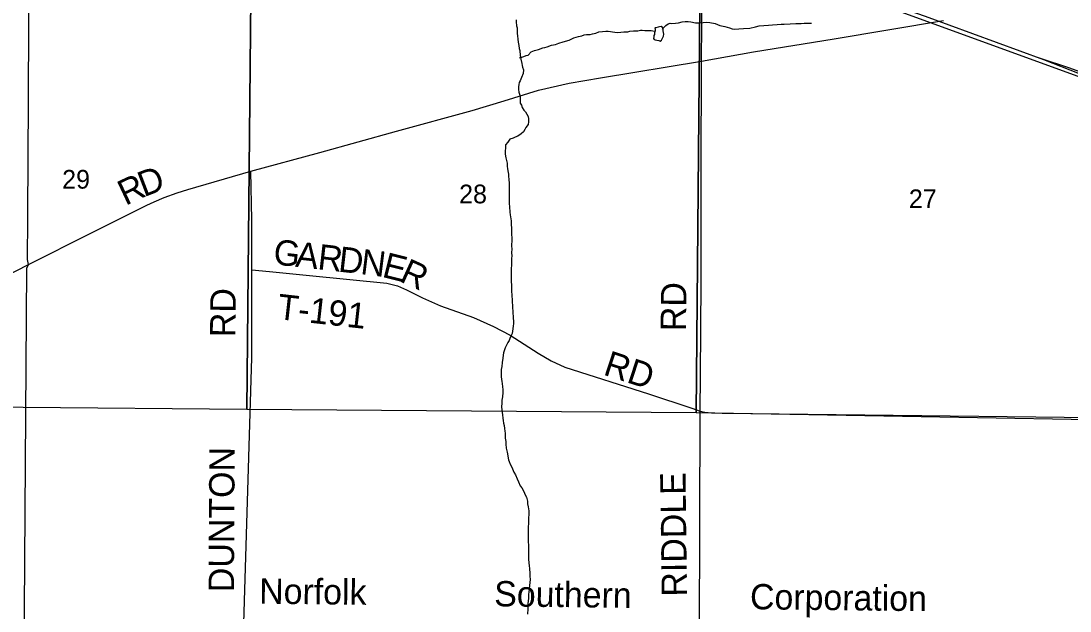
# Model space of a CAD drawing. Extents: x 0 to 34, y 0 to 22.
# Drawn here: x 4.651 to 6.998, y 14.74 to 16.061 of the extents above; entities that cross this region are included whole.
import ezdxf

# ---------------------------------------------------------------- set-up
doc = ezdxf.new("R2010")
doc.units = 0
for name, color, linetype in [('GM_X_County_Road', 7, 'Continuous'), ('GM_X_County_Road_Text', 7, 'Continuous'), ('GM_X_Minor_Lake', 7, 'Continuous'), ('GM_X_Minor_River', 7, 'Continuous'), ('GM_X_Rail_Line', 7, 'Continuous'), ('GM_X_Rail_Line_Text', 7, 'Continuous'), ('GM_X_Section', 7, 'Continuous'), ('GM_X_Section_Text', 7, 'Continuous'), ('GM_X_Township_Road', 7, 'Continuous'), ('GM_X_Township_Road_Text', 7, 'Continuous')]:
    doc.layers.add(name, color=color, linetype=linetype)

msp = doc.modelspace()

# ---------------------------------------------------------------- linework, layer by layer
at = {"layer": 'GM_X_County_Road'}
for points in [[(4.6673, 15.5158), (4.8067, 15.5856), (4.9325, 15.6484), (4.9491, 15.6559), (4.9713, 15.6652), (5.0005, 15.6759), (5.0239, 15.6838), (5.165, 15.7242), (5.3194, 15.7665), (5.4913, 15.8144), (5.6607, 15.8606), (5.7319, 15.8819), (5.8085, 15.906), (5.8772, 15.9212), (5.9478, 15.9336), (6.1734, 15.9709), (6.2896, 15.9914), (6.4702, 16.0208), (6.7149, 16.0617)], [(3.1578, 14.7935), (3.6526, 15.0232), (3.9337, 15.154), (4.0209, 15.1945), (4.1568, 15.2599), (4.2108, 15.2852), (4.2951, 15.3262), (4.5042, 15.4319), (4.6673, 15.5158)]]:
    msp.add_lwpolyline(points, dxfattribs=at)
at = {"layer": 'GM_X_Minor_Lake'}
msp.add_line((6.0699, 16.0454), (6.0692, 16.0448), dxfattribs=at)
msp.add_lwpolyline([(6.0692, 16.0448), (6.0699, 16.0422), (6.0699, 16.0384), (6.0687, 16.0342), (6.068, 16.0308), (6.0672, 16.0281), (6.0668, 16.0251), (6.0664, 16.0217), (6.0675, 16.019), (6.0701, 16.0186), (6.0735, 16.0178), (6.0777, 16.0167), (6.0807, 16.0155), (6.0838, 16.0181), (6.0853, 16.0208), (6.0872, 16.0234), (6.0884, 16.0264), (6.0892, 16.031), (6.0888, 16.0352), (6.0877, 16.0386), (6.0878, 16.0424), (6.0863, 16.0458), (6.0829, 16.0485), (6.0795, 16.0478), (6.0768, 16.047), (6.0715, 16.0452), (6.0699, 16.0454)], dxfattribs=at)
at = {"layer": 'GM_X_Minor_River'}
for points in [[(5.7585, 16.063), (5.7589, 16.0588), (5.7597, 16.0497), (5.7609, 16.0455), (5.7613, 16.0387), (5.7613, 16.0326), (5.7621, 16.0273)], [(6.086, 16.0424), (6.087, 16.0436), (6.0938, 16.0509), (6.0991, 16.0543), (6.1032, 16.0555), (6.1074, 16.0548), (6.115, 16.0556), (6.1222, 16.0567), (6.1306, 16.0587), (6.137, 16.0598), (6.1438, 16.0599), (6.1499, 16.0588), (6.1598, 16.0565), (6.1704, 16.0566), (6.1776, 16.0574), (6.1841, 16.0578), (6.1921, 16.0571), (6.2038, 16.0548), (6.2145, 16.0507), (6.2259, 16.0481), (6.2358, 16.0451), (6.2419, 16.0429), (6.2483, 16.0425), (6.257, 16.0429), (6.2673, 16.0441), (6.2813, 16.0449), (6.2942, 16.0473), (6.3029, 16.05), (6.3128, 16.0508), (6.3234, 16.0512), (6.3325, 16.052), (6.3428, 16.0528), (6.3519, 16.0533), (6.3587, 16.0537), (6.372, 16.0545), (6.3845, 16.0549), (6.3963, 16.0554), (6.4031, 16.0558), (6.41, 16.0558), (6.4145, 16.0562), (6.4198, 16.0562)], [(5.7659, 15.978), (5.7715, 15.9795), (5.776, 15.9814), (5.781, 15.9833), (5.7855, 15.9845), (5.7927, 15.9913), (5.7999, 15.9948), (5.809, 15.9967), (5.8184, 16.0006), (5.8226, 16.0017), (5.8279, 16.0025), (5.8378, 16.0068), (5.8465, 16.0083), (5.8541, 16.0114), (5.8643, 16.0137), (5.8772, 16.018), (5.8878, 16.0233), (5.898, 16.0257), (5.906, 16.0276), (5.9109, 16.0295), (5.9159, 16.0303), (5.9246, 16.0303), (5.9295, 16.0323), (5.9371, 16.0334), (5.9439, 16.0365), (5.9519, 16.0373), (5.9595, 16.0381), (5.9648, 16.0381), (5.9701, 16.0374), (5.9747, 16.0367), (5.9796, 16.0359), (5.9857, 16.0352), (5.9933, 16.0356), (5.9997, 16.0364), (6.0084, 16.0368), (6.013, 16.0376), (6.0213, 16.0384), (6.027, 16.0384), (6.0312, 16.0388), (6.0369, 16.04), (6.0411, 16.04), (6.0468, 16.0397), (6.054, 16.0393), (6.0612, 16.0393), (6.0684, 16.0379), (6.0692, 16.0374)], [(5.7621, 16.0273), (5.7629, 16.0201), (5.7633, 16.0136), (5.7645, 16.006), (5.7657, 15.9988), (5.7669, 15.9943), (5.768, 15.9836), (5.7692, 15.9753), (5.7712, 15.9654), (5.7723, 15.9612), (5.7731, 15.9571), (5.775, 15.9514), (5.7743, 15.9434), (5.771, 15.9339), (5.7676, 15.927), (5.7657, 15.9228), (5.7646, 15.9187), (5.7642, 15.913), (5.7643, 15.9076), (5.7647, 15.9012), (5.7677, 15.8921), (5.7678, 15.8769), (5.7709, 15.8723), (5.772, 15.8674), (5.7759, 15.8613), (5.7797, 15.8572), (5.7824, 15.8523), (5.7858, 15.8466), (5.7866, 15.8416), (5.7866, 15.8348), (5.7859, 15.8287), (5.7806, 15.8219), (5.7784, 15.8177), (5.7754, 15.8123), (5.7701, 15.8078), (5.7625, 15.8028), (5.7568, 15.8005), (5.7519, 15.7986), (5.7443, 15.7962), (5.7398, 15.7894), (5.7353, 15.7833), (5.7346, 15.7753), (5.7342, 15.7707), (5.7342, 15.7628), (5.7358, 15.7544), (5.7373, 15.748), (5.7385, 15.7427), (5.7389, 15.7347), (5.7393, 15.7305), (5.7405, 15.7256), (5.7417, 15.718), (5.7417, 15.7134), (5.7425, 15.7058), (5.7433, 15.6975), (5.7435, 15.6523), (5.7439, 15.6447), (5.7448, 15.6329), (5.7455, 15.6264), (5.7471, 15.6177), (5.7475, 15.6132), (5.7479, 15.6056), (5.7484, 15.5961), (5.7484, 15.5828), (5.7488, 15.5752), (5.7489, 15.5706), (5.7486, 15.5573), (5.749, 15.5497), (5.7486, 15.5425), (5.749, 15.5341), (5.7487, 15.53), (5.7487, 15.5254), (5.7484, 15.5193), (5.748, 15.5148), (5.7477, 15.506), (5.7473, 15.4992), (5.7473, 15.495), (5.7478, 15.4886), (5.7474, 15.4772), (5.7482, 15.4692), (5.7483, 15.4646), (5.7487, 15.4578), (5.7491, 15.4449), (5.7499, 15.4369), (5.7499, 15.432), (5.7507, 15.4229), (5.7512, 15.4069), (5.752, 15.3989), (5.752, 15.3947), (5.7528, 15.3891), (5.7532, 15.3826), (5.7521, 15.3784), (5.7514, 15.3716), (5.7506, 15.3666), (5.7495, 15.3613), (5.7469, 15.3552), (5.7447, 15.3499), (5.7428, 15.3457), (5.7398, 15.3407), (5.7368, 15.3347), (5.7345, 15.3286), (5.7308, 15.3179)], [(5.7308, 15.3179), (5.73, 15.3122), (5.7289, 15.3061), (5.7275, 15.2959), (5.7264, 15.2871), (5.7253, 15.2807), (5.7253, 15.2643), (5.7265, 15.2537), (5.7277, 15.2491), (5.7281, 15.2415), (5.7293, 15.2358), (5.7293, 15.2286), (5.7279, 15.2191), (5.7268, 15.2119), (5.7264, 15.2054), (5.7261, 15.1971), (5.7265, 15.1899), (5.7273, 15.1842), (5.7281, 15.1792), (5.7288, 15.1716), (5.7296, 15.1663), (5.7308, 15.1599), (5.7316, 15.1553), (5.7324, 15.1481), (5.7336, 15.1424), (5.734, 15.1375), (5.7344, 15.1265), (5.7356, 15.1189), (5.7356, 15.1136), (5.7364, 15.1041), (5.7383, 15.0953), (5.7418, 15.0783), (5.743, 15.0741), (5.7457, 15.0684), (5.7488, 15.062), (5.7538, 15.0502), (5.7572, 15.0445), (5.7614, 15.0358), (5.7641, 15.029), (5.768, 15.0203), (5.7718, 15.0157), (5.776, 15.007), (5.7791, 14.9998), (5.7821, 14.9945), (5.7844, 14.9858), (5.7845, 14.9797), (5.7856, 14.9729), (5.7872, 14.9641), (5.7872, 14.9573), (5.7865, 14.9467), (5.7862, 14.9402), (5.7862, 14.9356), (5.7855, 14.9284), (5.7856, 14.8988), (5.786, 14.8931), (5.7861, 14.8889), (5.7861, 14.8794), (5.7862, 14.8551), (5.787, 14.8483), (5.7878, 14.8399), (5.7886, 14.8357), (5.7891, 14.8228), (5.7895, 14.8179), (5.7899, 14.8103), (5.7895, 14.8035), (5.7884, 14.7966), (5.7877, 14.789), (5.787, 14.7818), (5.7866, 14.7776), (5.7863, 14.7685), (5.7856, 14.762), (5.7852, 14.7567), (5.7852, 14.7514), (5.7849, 14.7442), (5.7842, 14.7328)]]:
    msp.add_lwpolyline(points, dxfattribs=at)
at = {"layer": 'GM_X_Rail_Line'}
for points in [[(2.1205, 17.682), (2.6475, 17.5103), (3.1194, 17.3438), (3.8981, 17.0634), (4.4129, 16.8774), (5.5123, 16.484), (6.2938, 16.2008), (7.1773, 15.8785), (7.9469, 15.6046), (8.6994, 15.3378), (8.9, 15.264)], [(4.3626, 16.8993), (4.9898, 16.6747), (5.3844, 16.533), (5.7561, 16.3995), (6.08, 16.2832), (6.1965, 16.2416), (6.2568, 16.2199), (6.33, 16.1936), (6.5817, 16.1037), (6.6739, 16.0713), (6.9385, 15.9745), (7.0187, 15.9431)], [(6.9289, 15.978), (6.9967, 15.9559), (7.042, 15.9395), (7.1188, 15.9123), (7.1899, 15.8865), (7.2178, 15.8734), (7.2723, 15.8542), (7.4638, 15.785), (7.7247, 15.6929), (7.953, 15.611), (8.0653, 15.5682), (8.2472, 15.5053), (8.4865, 15.4197), (8.8012, 15.3067), (8.8315, 15.296), (8.8453, 15.2914), (8.8602, 15.2877), (8.8738, 15.2847), (8.8918, 15.2814), (8.9, 15.2794)]]:
    msp.add_lwpolyline(points, dxfattribs=at)
at = {"layer": 'GM_X_Section'}
for points in [[(4.1651, 16.2036), (5.166, 16.1912), (5.1562, 15.1911), (4.1541, 15.2001)], [(5.166, 16.1912), (6.1703, 16.1807), (6.1617, 15.1831), (5.1562, 15.1911)], [(7.1762, 16.1739), (7.1686, 15.1654), (6.1617, 15.1831), (6.1703, 16.1807)]]:
    msp.add_lwpolyline(points, close=True, dxfattribs=at)
at = {"layer": 'GM_X_Township_Road'}
msp.add_line((6.1678, 14.1796), (6.1703, 15.1871), dxfattribs=at)
for points in [[(6.1734, 15.9709), (6.1751, 16.1354), (6.1772, 16.3363), (6.1789, 16.4878), (6.1793, 16.4965)], [(4.6673, 15.5158), (4.6653, 15.5268), (4.6662, 15.6195), (4.667, 15.7615), (4.6675, 15.8759), (4.6678, 15.9349), (4.6683, 16.0047), (4.6686, 16.0899)], [(6.1703, 15.1871), (6.1711, 15.2669), (6.1725, 15.4753), (6.1725, 15.7256), (6.1734, 15.9709)], [(5.1485, 14.688), (5.1676, 15.3066), (5.1671, 15.5037), (5.1673, 15.6155), (5.165, 15.7242)], [(4.655, 14.1959), (4.6642, 15.507), (4.6673, 15.5158)], [(5.1671, 15.5037), (5.2071, 15.4995), (5.2966, 15.4906), (5.4696, 15.4739), (5.493, 15.4679), (5.5132, 15.4587), (5.549, 15.4406), (5.5898, 15.4232), (5.6631, 15.397), (5.7081, 15.3768), (5.7454, 15.3576), (5.8078, 15.3169), (5.8372, 15.2995), (5.868, 15.286), (6.0552, 15.226), (6.1521, 15.1938), (6.1703, 15.1871)], [(6.1703, 15.1871), (6.1806, 15.1847), (6.196, 15.1833), (6.2197, 15.1828), (7.1768, 15.1715)]]:
    msp.add_lwpolyline(points, dxfattribs=at)

# ---------------------------------------------------------------- texts
at = {"layer": 'GM_X_County_Road_Text'}
for s, rotation, p in [('D', 20.9193, (4.9257, 15.666)), ('R', 25.1371, (4.8845, 15.6466))]:
    msp.add_text(s, height=0.0568, rotation=rotation, dxfattribs=at).set_placement(p)
at = {"layer": 'GM_X_Rail_Line_Text'}
for s, height, rotation, p in [('Norfolk', 0.05663, 359.349, (5.1836, 14.7562)), ('Southern', 0.05663, 359.3031, (5.7095, 14.7503)), ('Corporation', 0.056629, 359.3598, (6.2819, 14.7437))]:
    msp.add_text(s, height=height, rotation=rotation, dxfattribs=at).set_placement(p)
at = {"layer": 'GM_X_Section_Text'}
for s, p in [('29', (4.7429, 15.6854)), ('28', (5.6312, 15.6525)), ('27', (6.6375, 15.6417))]:
    msp.add_text(s, height=0.04186, rotation=0, dxfattribs=at).set_placement(p)
at = {"layer": 'GM_X_Township_Road_Text'}
for s, height, rotation, p in [('G', 0.0568, 353.5256, (5.2136, 15.5163)), ('A', 0.0568, 353.5259, (5.2633, 15.5107)), ('R', 0.0568, 353.5253, (5.3129, 15.5051)), ('D', 0.0568, 353.5148, (5.3593, 15.4998)), ('N', 0.0568, 352.8691, (5.4088, 15.4942)), ('E', 0.0568, 345.8692, (5.4566, 15.4883)), ('R', 0.0568, 335.509, (5.4953, 15.4788)), ('RD', 0.05682, 89.5045, (6.1388, 15.366)), ('RD', 0.05682, 89.5063, (5.1305, 15.3526)), ('T-191', 0.05682, 353.5975, (5.2226, 15.3935)), ('RD', 0.05682, 341.8777, (5.9515, 15.2695)), ('DUNTON', 0.05682, 89.6746, (5.1272, 14.7817)), ('RIDDLE', 0.05682, 90.7492, (6.1413, 14.7722))]:
    msp.add_text(s, height=height, rotation=rotation, dxfattribs=at).set_placement(p)

doc.saveas('drawing.dxf')
